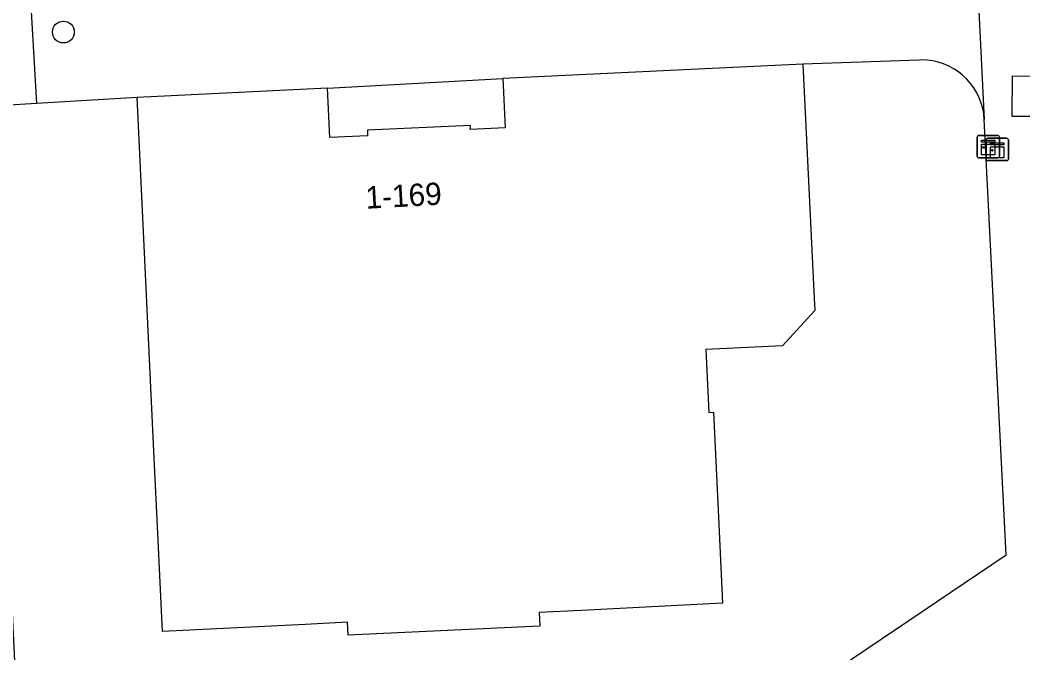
# Model space of a CAD drawing. Extents: x 161084 to 161928, y 385355 to 386522.
# Drawn here: x 161590.48 to 161635.42, y 385400.5 to 385428.86 of the extents above; entities that cross this region are included whole.
import ezdxf

# ---------------------------------------------------------------- set-up
doc = ezdxf.new("R2010")
doc.units = 0
for name, color, linetype in [('IMGEO_Boom', 7, 'Continuous'), ('IMGEO_Kast', 7, 'Continuous'), ('IMGEO_Pand', 7, 'Continuous'), ('IMGEO_Pand_nummerreeks', 7, 'Continuous'), ('IMGEO_Voetpad_open', 7, 'Continuous')]:
    doc.layers.add(name, color=color, linetype=linetype)

msp = doc.modelspace()

# ---------------------------------------------------------------- linework, layer by layer
at = {"layer": 'IMGEO_Boom'}
msp.add_circle((161592.418, 385428.319), 0.489, dxfattribs=at)
at = {"layer": 'IMGEO_Kast'}
for p, q in [((161633.37, 385422.76), (161633.37, 385423.601)), ((161633.37, 385423.601), (161633.37, 385422.76)), ((161633.445, 385423.685), (161634.286, 385423.685)), ((161634.286, 385423.685), (161633.445, 385423.685)), ((161633.848, 385423.561), (161634.689, 385423.561)), ((161634.689, 385423.561), (161633.848, 385423.561)), ((161634.37, 385423.61), (161634.37, 385422.769)), ((161634.37, 385422.769), (161634.37, 385423.61)), ((161633.773, 385422.636), (161633.773, 385423.477)), ((161633.773, 385423.477), (161633.773, 385422.636)), ((161634.773, 385423.486), (161634.773, 385422.645)), ((161634.773, 385422.645), (161634.773, 385423.486)), ((161634.295, 385422.685), (161633.454, 385422.685)), ((161633.454, 385422.685), (161634.295, 385422.685)), ((161634.698, 385422.561), (161633.857, 385422.561)), ((161633.857, 385422.561), (161634.698, 385422.561))]:
    msp.add_line(p, q, dxfattribs=at)
for points in [[(161633.565, 385423.475), (161634.165, 385423.475), (161634.165, 385423.39), (161633.565, 385423.39), (161633.565, 385423.475)], [(161633.565, 385423.3), (161634.165, 385423.3), (161634.165, 385422.811), (161633.565, 385422.811), (161633.565, 385423.3)], [(161633.968, 385423.351), (161634.568, 385423.351), (161634.568, 385423.266), (161633.968, 385423.266), (161633.968, 385423.351)], [(161633.968, 385423.176), (161634.568, 385423.176), (161634.568, 385422.687), (161633.968, 385422.687), (161633.968, 385423.176)]]:
    msp.add_lwpolyline(points, dxfattribs=at)
for centre in [(161633.649, 385423.149), (161634.052, 385423.025)]:
    msp.add_circle(centre, 0.0377, dxfattribs=at)
for centre, start, end in [((161633.448, 385423.607), 92.4484, 184.2845), ((161633.448, 385423.607), 92.4484, 184.2845), ((161633.851, 385423.483), 92.4484, 184.2845), ((161633.851, 385423.483), 92.4484, 184.2845), ((161634.292, 385423.607), 2.4484, 94.2845), ((161634.292, 385423.607), 2.4484, 94.2845), ((161634.695, 385423.483), 2.4484, 94.2845), ((161634.695, 385423.483), 2.4484, 94.2845), ((161633.448, 385422.763), 182.4484, 274.2845), ((161633.448, 385422.763), 182.4484, 274.2845), ((161633.851, 385422.639), 182.4484, 274.2845), ((161633.851, 385422.639), 182.4484, 274.2845), ((161634.292, 385422.763), 272.4484, 4.2845), ((161634.292, 385422.763), 272.4484, 4.2845), ((161634.695, 385422.639), 272.4484, 4.2845), ((161634.695, 385422.639), 272.4484, 4.2845)]:
    msp.add_arc(centre, 0.0779, start, end, dxfattribs=at)
at = {"layer": 'IMGEO_Pand'}
for points in [[(161625.562, 385426.877), (161626.064, 385416.404), (161626.091, 385415.847), (161624.648, 385414.259), (161621.216, 385414.095), (161621.351, 385411.281), (161621.547, 385411.29), (161621.772, 385406.593), (161621.957, 385402.727), (161615.643, 385402.409), (161613.745, 385402.313), (161613.774, 385401.71), (161605.184, 385401.298), (161605.156, 385401.88), (161603.258, 385401.784), (161596.866, 385401.462), (161596.656, 385405.848), (161596.494, 385409.222), (161595.917, 385421.278), (161595.72, 385425.39)], [(161625.562, 385426.877), (161612.112, 385426.233)], [(161612.112, 385426.233), (161612.217, 385424.032), (161610.649, 385423.948), (161610.659, 385424.133), (161606.041, 385423.926), (161606.053, 385423.676), (161604.365, 385423.595), (161604.26, 385425.799)], [(161604.26, 385425.799), (161595.72, 385425.39)]]:
    msp.add_lwpolyline(points, dxfattribs=at)
at = {"layer": 'IMGEO_Voetpad_open'}
for points in [[(161633.288, 385432.635), (161633.689, 385424.4)], [(161590.893, 385430.537), (161591.22, 385425.118)], [(161633.689, 385424.4), (161633.665, 385424.65), (161633.619, 385424.897), (161633.551, 385425.139), (161633.462, 385425.374), (161633.352, 385425.6), (161633.222, 385425.815), (161633.074, 385426.018), (161632.908, 385426.206), (161632.726, 385426.379), (161632.529, 385426.536), (161632.319, 385426.674), (161632.098, 385426.792), (161631.867, 385426.891), (161631.628, 385426.968), (161631.383, 385427.024), (161631.134, 385427.057), (161630.883, 385427.068), (161630.767, 385427.066), (161625.562, 385426.877)], [(161604.26, 385425.799), (161612.112, 385426.233)], [(161636.665, 385426.336), (161636.679, 385424.531), (161634.943, 385424.536), (161634.961, 385426.354), (161636.665, 385426.336)], [(161595.72, 385425.39), (161591.22, 385425.118)], [(161591.22, 385425.118), (161588.997, 385424.984), (161590.658, 385391.255)], [(161616.542, 385392.668), (161634.672, 385404.896), (161633.689, 385424.4)]]:
    msp.add_lwpolyline(points, dxfattribs=at)

# ---------------------------------------------------------------- texts
at = {"layer": 'IMGEO_Pand_nummerreeks'}
msp.add_text('1-169', height=1, rotation=3.1855, dxfattribs=at).set_placement((161605.984, 385420.4))

doc.saveas('drawing.dxf')
